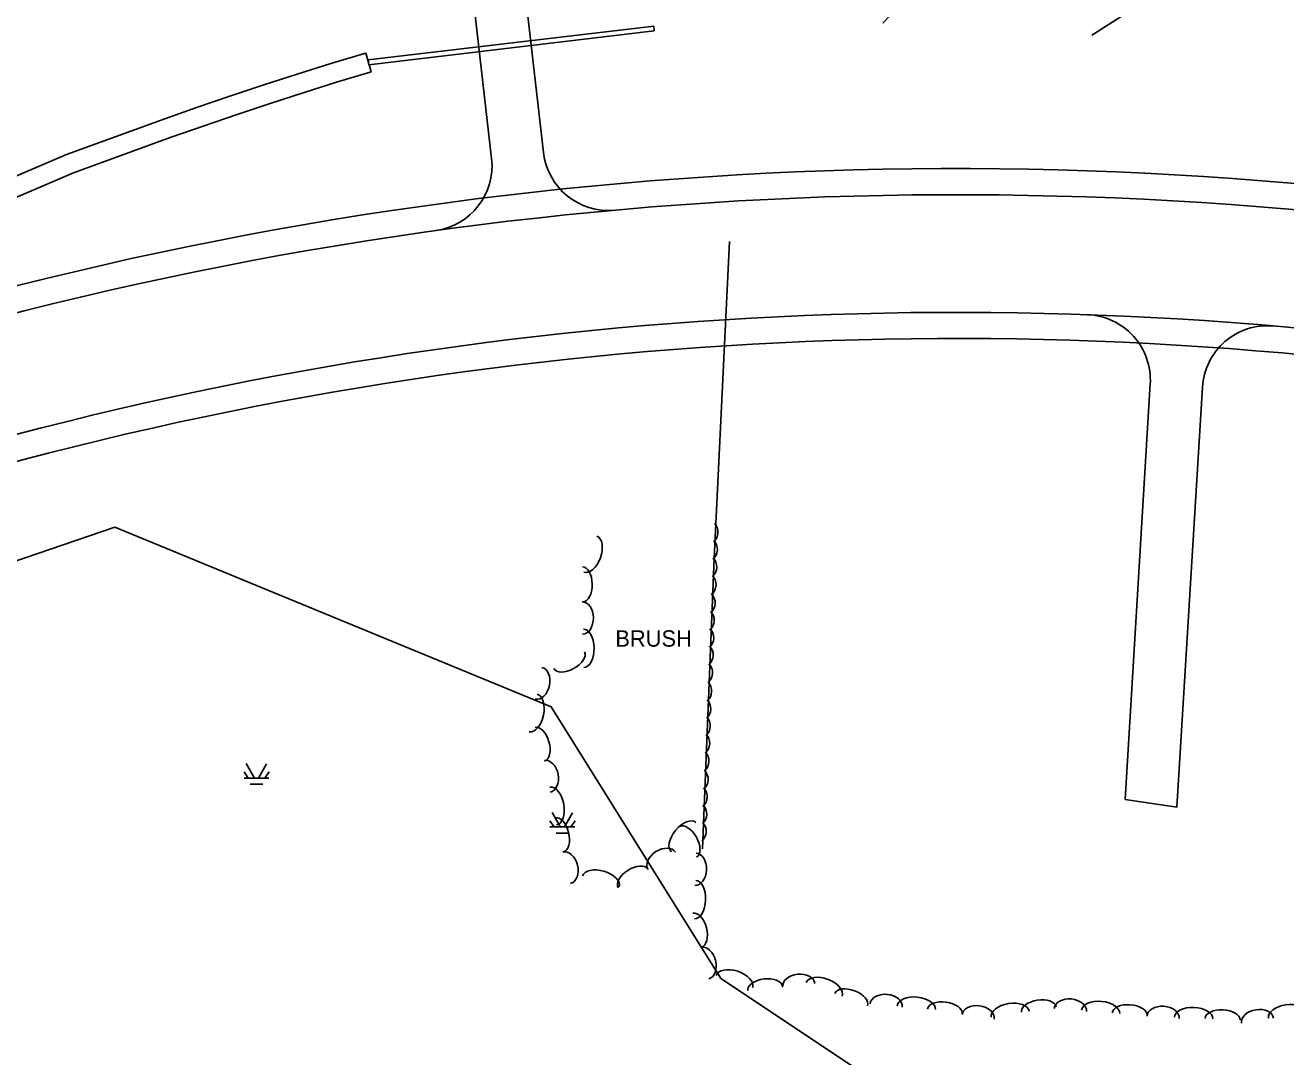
# Model space of a CAD drawing. Extents: x 978516 to 993312, y 1836504 to 1846212.
# Drawn here: x 991462.3 to 991848.1, y 1839388.9 to 1839704.5 of the extents above; entities that cross this region are included whole.
import ezdxf

# ---------------------------------------------------------------- set-up
doc = ezdxf.new("R2010")
doc.units = 0
for name, color, linetype in [('R_CONCRETE', 7, 'Continuous'), ('R_Drainage', 7, 'Continuous'), ('R_Proposed Road', 7, 'Continuous'), ('S_STREAM', 7, 'Continuous'), ('S_TREE', 7, 'Continuous'), ('S_TREE_ANNOT', 7, 'Continuous')]:
    doc.layers.add(name, color=color, linetype=linetype)

msp = doc.modelspace()

# ---------------------------------------------------------------- linework, layer by layer
at = {"layer": 'R_CONCRETE'}
for p, q in [((991567.33, 1839693.15), (991566.48, 1839696.02)), ((991568.18, 1839690.27), (991567.55, 1839692.42))]:
    msp.add_line(p, q, dxfattribs=at)
for points in [[(991474.86, 1839664.92), (991504.95, 1839675.86), (991515.03, 1839679.42), (991525.16, 1839682.89), (991535.32, 1839686.27), (991545.53, 1839689.57), (991555.78, 1839692.78), (991566.07, 1839695.9), (991566.48, 1839696.02)], [(991477.06, 1839659.34), (991506.97, 1839670.22), (991517, 1839673.75), (991527.08, 1839677.21), (991537.19, 1839680.57), (991547.35, 1839683.85), (991557.55, 1839687.05), (991567.79, 1839690.15), (991568.18, 1839690.27)], [(991416.47, 1839639.46), (991426.07, 1839643.89), (991435.75, 1839648.23), (991445.48, 1839652.47), (991474.86, 1839664.92)], [(991418.98, 1839634.01), (991428.56, 1839638.43), (991438.17, 1839642.74), (991447.85, 1839646.96), (991477.06, 1839659.34)]]:
    msp.add_lwpolyline(points, dxfattribs=at)
at = {"layer": 'R_Drainage'}
for p, q in [((991567.24, 1839693.89), (991654.63, 1839704.28)), ((991654.63, 1839704.28), (991654.8, 1839702.79)), ((991567.42, 1839692.4), (991654.8, 1839702.79)), ((991567.24, 1839693.89), (991567.42, 1839692.4))]:
    msp.add_line(p, q, dxfattribs=at)
at = {"layer": 'R_Proposed Road'}
msp.add_line((991798.88, 1839467.63), (991814.76, 1839465.27), dxfattribs=at)
for points in [[(991608.69, 1839772.31), (991620.9, 1839665.56)], [(991593.13, 1839767.59), (991605, 1839663.75)], [(991806.6, 1839594.75), (991798.88, 1839467.63)], [(991822.57, 1839593.78), (991814.76, 1839465.27)]]:
    msp.add_lwpolyline(points, dxfattribs=at)
for centre, radius, start, end in [((991640.77, 1839667.84), 20, 186.5251, 275.1699), ((991585.13, 1839661.47), 20, 277.8803, 6.5251), ((991747.45, 1838488.74), 1171.92, 67.29702, 123.64915), ((991747.45, 1838488.74), 1163.92, 67.29702, 123.64915), ((991747.45, 1838488.74), 1127.92, 70.20618, 123.64915), ((991786.63, 1839595.96), 20, 356.5251, 87.9732), ((991842.53, 1839592.57), 20, 85.0769, 176.5251), ((991747.45, 1838488.74), 1119.92, 70.20618, 123.64915)]:
    msp.add_arc(centre, radius, start, end, dxfattribs=at)
at = {"layer": 'S_STREAM'}
for p, q in [((991529.22, 1839476.03), (991530.53, 1839474.13)), ((991529.91, 1839478.59), (991532.43, 1839474.09)), ((991536.15, 1839478.47), (991533.67, 1839474.13)), ((991536.89, 1839476.03), (991535.57, 1839474.13)), ((991529.22, 1839474.17), (991536.81, 1839474.13)), ((991531.15, 1839472.27), (991534.95, 1839472.27)), ((991622.86, 1839461.08), (991624.18, 1839459.18)), ((991623.56, 1839463.63), (991626.08, 1839459.14)), ((991629.8, 1839463.52), (991627.32, 1839459.18)), ((991630.54, 1839461.08), (991629.22, 1839459.18)), ((991622.86, 1839459.22), (991630.46, 1839459.18)), ((991624.8, 1839457.32), (991628.6, 1839457.32))]:
    msp.add_line(p, q, dxfattribs=at)
for points in [[(991724.71, 1839705.13), (991733.59, 1839714.68), (991746.61, 1839724.88), (991780.35, 1839739.95), (991800.13, 1839750.38), (991814.31, 1839750.67), (991821.53, 1839748.67), (991825.19, 1839745.68), (991825.79, 1839730.34), (991824.19, 1839724.54), (991810.95, 1839715.72), (991789.18, 1839701.83), (991788.69, 1839701.48)], [(991146.16, 1839433.54), (991489.7, 1839550.88), (991623.28, 1839495.97), (991675.21, 1839412.82), (991819.69, 1839316.57), (991825.3, 1839248.51), (991800.02, 1839187.41), (991787.28, 1839177), (991747.13, 1839177.55), (991714.82, 1839178.96), (991711.59, 1839131.85), (991753.47, 1839114.1), (991769.45, 1839079.18), (991740.61, 1839037.46), (991618.64, 1838989.31), (991584.86, 1838966.19)]]:
    msp.add_lwpolyline(points, dxfattribs=at)
at = {"layer": 'S_TREE'}
msp.add_lwpolyline([(991677.78, 1839638.33), (991673.09, 1839541.46), (991669.56, 1839452.5)], dxfattribs=at)
for centre, major_axis, ratio, start_param, end_param in [((991670.98, 1839549.38), (0.08, 3.64), 0.909767, 3.796151, 5.569352), ((991635.26, 1839542.64), (1.99, 5.52), 0.55043, 3.14178, 6.283372), ((991670.8, 1839544.1), (0.08, 3.64), 0.909767, 3.796151, 5.569352), ((991670.6, 1839538.77), (0.08, 3.64), 0.909767, 3.805668, 5.578869), ((991632.9, 1839533.43), (-0.07, 5.35), 0.540692, 3.141593, 6.283185), ((991670.38, 1839533.34), (0.08, 3.64), 0.909767, 3.805668, 5.578869), ((991670.12, 1839527.7), (0.08, 3.64), 0.909767, 3.805668, 5.578869), ((991632.77, 1839523.12), (-0.07, 4.96), 0.685301, 3.141593, 6.283185), ((991669.84, 1839522.37), (0.08, 3.64), 0.909767, 3.805668, 5.578869), ((991633.16, 1839513.87), (-0.08, 5.87), 0.550072, 3.141593, 6.283185), ((991669.7, 1839517.09), (0.08, 3.64), 0.909767, 3.805668, 5.578869), ((991669.52, 1839511.79), (0.08, 3.64), 0.909767, 3.805668, 5.578869), ((991628.74, 1839510.2), (4.7, 2.55), 0.540687, 3.141593, 6.283185), ((991619.38, 1839503.15), (1.02, 4.85), 0.685298, 3.141593, 6.283185), ((991669.31, 1839506.35), (0.08, 3.64), 0.909767, 3.805668, 5.578869), ((991669.05, 1839500.71), (0.08, 3.64), 0.909767, 3.805668, 5.578869), ((991617.72, 1839494.04), (1.21, 5.74), 0.550069, 3.141593, 6.283185), ((991668.77, 1839495.38), (0.08, 3.64), 0.909767, 3.805668, 5.578869), ((991668.63, 1839490.1), (0.08, 3.64), 0.909767, 3.805668, 5.578869), ((991619.77, 1839484.48), (-1.47, 5.14), 0.540695, 3.141593, 6.283185), ((991668.45, 1839484.8), (0.08, 3.64), 0.909767, 3.805668, 5.578869), ((991622.02, 1839474.68), (-0.86, 4.88), 0.685304, 3.141593, 6.283185), ((991668.23, 1839479.36), (0.08, 3.64), 0.909767, 3.805668, 5.578869), ((991667.98, 1839473.72), (0.08, 3.64), 0.909767, 3.805668, 5.578869), ((991623.89, 1839465.6), (-1.02, 5.78), 0.550075, 3.141593, 6.283185), ((991667.7, 1839468.39), (0.08, 3.64), 0.909767, 3.805668, 5.578869), ((991667.56, 1839463.11), (0.08, 3.64), 0.909767, 3.805668, 5.578869), ((991625.78, 1839456.8), (-1.28, 5.19), 0.540695, 3.141593, 6.283185), ((991663.79, 1839456.07), (-3.74, -4.52), 0.550066, 3.141593, 6.283185), ((991667.38, 1839457.81), (0.08, 3.64), 0.909767, 3.805668, 5.578869), ((991665.15, 1839454.66), (-2.58, 4.68), 0.540698, 3.141593, 6.283185), ((991657.1, 1839448.78), (-4.18, -2.66), 0.685295, 3.141593, 6.283185), ((991627.99, 1839446.73), (-1.19, 4.81), 0.685305, 3.141593, 6.283185), ((991667.38, 1839446.22), (0.19, 4.95), 0.685301, 3.141593, 6.283185), ((991638.47, 1839442.53), (-5.62, 1.67), 0.550077, 3.141593, 6.283185), ((991648.26, 1839443.46), (-4.51, -2.87), 0.540687, 3.141593, 6.283185), ((991667.29, 1839436.96), (0.22, 5.86), 0.550072, 3.141593, 6.283185), ((991667.95, 1839427.59), (-1.33, 5.18), 0.540695, 3.141593, 6.283185), ((991670.26, 1839417.54), (-1.23, 4.8), 0.685305, 3.141593, 6.283185), ((991679.33, 1839411.94), (-5.58, 1.83), 0.550077, 3.141593, 6.283185), ((991699, 1839410.75), (-4.92, -0.58), 0.685301, 3.141593, 6.283185), ((991688.74, 1839409.8), (-5.31, -0.63), 0.540692, 3.141593, 6.283185), ((991706.81, 1839409.53), (-5.48, 2.11), 0.550078, 3.141593, 6.283185), ((991715.09, 1839406.34), (-4.99, 1.92), 0.540698, 3.141593, 6.283185), ((991725.78, 1839404.56), (-4.93, 0.5), 0.685305, 3.141593, 6.283185), ((991735.02, 1839403.89), (-5.84, 0.59), 0.550075, 3.141593, 6.283185), ((991772.48, 1839403.32), (-5.28, -0.84), 0.540691, 3.141593, 6.283185), ((991782.15, 1839403.17), (-4.93, 0.45), 0.685304, 3.141593, 6.283185), ((991743.74, 1839402.73), (-5.3, 0.72), 0.540695, 3.141593, 6.283185), ((991753.91, 1839401.08), (-4.91, 0.67), 0.685305, 3.141593, 6.283185), ((991763.72, 1839401.93), (-5.8, -0.92), 0.550071, 3.141593, 6.283185), ((991791.4, 1839402.59), (-5.84, 0.53), 0.550075, 3.141593, 6.283185), ((991800.28, 1839401.91), (-5.33, 0.37), 0.540694, 3.141593, 6.283185), ((991810.55, 1839400.94), (-4.94, 0.34), 0.685304, 3.141593, 6.283185), ((991819.87, 1839400.73), (-5.86, 0.25), 0.550074, 3.141593, 6.283185), ((991828.73, 1839400.35), (-5.34, 0.23), 0.540694, 3.141593, 6.283185), ((991839.46, 1839399.91), (-4.9, -0.75), 0.6853, 3.141593, 6.283185), ((991848.57, 1839401.58), (-5.8, -0.89), 0.550071, 3.141593, 6.283185)]:
    msp.add_ellipse(centre, major_axis=major_axis, ratio=ratio, start_param=start_param, end_param=end_param, dxfattribs=at)

# ---------------------------------------------------------------- texts
at = {"layer": 'S_TREE_ANNOT'}
msp.add_text('BRUSH', height=5, dxfattribs=at).set_placement((991642.88, 1839514.36))

doc.saveas('drawing.dxf')
